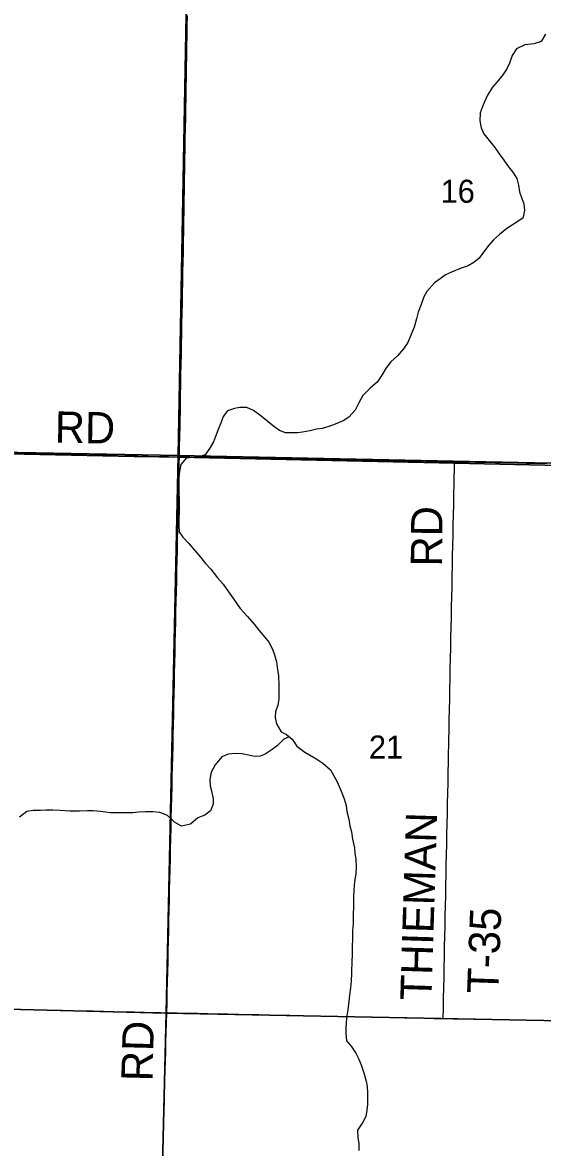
# Model space of a CAD drawing. Extents: x 0 to 34, y 0 to 22.
# Drawn here: x 3.484 to 4.43, y 15.194 to 17.239 of the extents above; entities that cross this region are included whole.
import ezdxf

# ---------------------------------------------------------------- set-up
doc = ezdxf.new("R2010")
doc.units = 0
for name, color, linetype in [('GM_X_Corporation', 7, 'Continuous'), ('GM_X_County_Road', 7, 'Continuous'), ('GM_X_County_Road_Text', 7, 'Continuous'), ('GM_X_Minor_River', 7, 'Continuous'), ('GM_X_Section_Text', 7, 'Continuous'), ('GM_X_State_Route', 7, 'Continuous'), ('GM_X_Township_Road', 7, 'Continuous'), ('GM_X_Township_Road_Text', 7, 'Continuous')]:
    doc.layers.add(name, color=color, linetype=linetype)

msp = doc.modelspace()

# ---------------------------------------------------------------- linework, layer by layer
at = {"layer": 'GM_X_Corporation'}
for points in [[(3.5996, 19.4692), (2.7976, 19.484), (2.7779, 19.4843), (2.1, 19.4964), (2.1, 16.485), (2.253, 16.4822), (2.4333, 16.478), (2.4403, 16.4778), (2.5826, 16.473), (2.7595, 16.4724), (3.1897, 16.4617), (3.4295, 16.4557), (3.687, 16.4502), (3.6948, 16.4501), (3.7682, 16.4494), (4.2697, 16.4379), (4.8738, 16.4249)], [(4.8738, 16.4249), (4.2697, 16.4379), (3.7682, 16.4494), (3.6948, 16.4501), (3.687, 16.4502), (3.4295, 16.4557), (3.1897, 16.4617), (2.7595, 16.4724), (2.5826, 16.473), (2.4403, 16.4778), (2.4333, 16.478), (2.253, 16.4822), (2.1, 16.485), (2.1, 14.1), (7.7244, 14.1)]]:
    msp.add_lwpolyline(points, dxfattribs=at)
for points in [[(3.785, 17.4549), (3.7672, 16.4521), (2.7618, 16.4707), (2.771, 17.4824)], [(4.7862, 17.4375), (4.7695, 16.4317), (3.7672, 16.4521), (3.785, 17.4549)], [(2.7618, 16.4707), (3.7672, 16.4521), (3.745, 15.438), (2.7333, 15.4639)], [(4.7695, 16.4317), (4.7451, 15.4188), (3.745, 15.438), (3.7672, 16.4521)], [(3.745, 15.438), (3.7208, 14.432), (2.7064, 14.4541), (2.7333, 15.4639)], [(4.7451, 15.4188), (4.7262, 14.4138), (3.7208, 14.432), (3.745, 15.438)]]:
    msp.add_lwpolyline(points, close=True, dxfattribs=at)
at = {"layer": 'GM_X_County_Road'}
msp.add_lwpolyline([(3.4702, 16.4561), (3.4889, 16.4558), (3.5075, 16.4554), (3.5261, 16.455), (3.5448, 16.4546), (3.5634, 16.4542), (3.582, 16.4538), (3.6007, 16.4534), (3.6193, 16.453), (3.6379, 16.4526), (3.6566, 16.4522), (3.6752, 16.4518), (3.6938, 16.4514), (3.7125, 16.451), (3.7311, 16.4506), (3.7497, 16.4502), (3.7596, 16.45), (3.7694, 16.4498), (3.7881, 16.4495), (3.8067, 16.4492), (3.8253, 16.4488), (3.844, 16.4485), (3.8626, 16.4482), (3.8813, 16.4478), (3.8999, 16.4475), (3.9185, 16.4472), (3.9372, 16.4468), (3.9558, 16.4465), (3.9745, 16.4462), (3.9931, 16.4458), (4.0117, 16.4455), (4.0304, 16.4452), (4.049, 16.4448), (4.0677, 16.4445), (4.0863, 16.4442), (4.105, 16.4438), (4.1236, 16.4435), (4.1422, 16.4432), (4.1609, 16.4428), (4.1795, 16.4425), (4.1982, 16.4422), (4.2168, 16.4418), (4.2354, 16.4415), (4.2528, 16.4412), (4.2701, 16.4409), (4.2887, 16.4405), (4.3074, 16.4402), (4.326, 16.4398), (4.3446, 16.4395), (4.3633, 16.4391), (4.3819, 16.4388), (4.4005, 16.4384), (4.4192, 16.4381), (4.4378, 16.4377)], dxfattribs=at)
at = {"layer": 'GM_X_Minor_River'}
for points in [[(4.4358, 17.2183), (4.428, 17.2051), (4.4146, 17.2009), (4.3979, 17.1986), (4.3829, 17.1917), (4.3747, 17.1794), (4.3702, 17.1654), (4.3654, 17.1549), (4.358, 17.144), (4.3475, 17.1317), (4.3389, 17.1216), (4.3302, 17.1074), (4.3243, 17.0949), (4.3203, 17.0851), (4.3166, 17.0753), (4.3159, 17.0609), (4.3183, 17.0479), (4.3234, 17.0371), (4.3356, 17.022), (4.3437, 17.0123), (4.3514, 17.0007), (4.3595, 16.9891), (4.3665, 16.9795), (4.3772, 16.9655), (4.3834, 16.9559), (4.3866, 16.9436), (4.3882, 16.9318), (4.3925, 16.9195), (4.3961, 16.9099), (4.3977, 16.8977), (4.3944, 16.8837), (4.3786, 16.8735), (4.3651, 16.8647), (4.3516, 16.8539), (4.3411, 16.8443), (4.3326, 16.8346), (4.3228, 16.8219), (4.315, 16.8107), (4.3053, 16.8033), (4.2946, 16.7971), (4.2823, 16.7928), (4.2647, 16.7856), (4.2536, 16.7805), (4.244, 16.7735), (4.2339, 16.7658), (4.2199, 16.7505), (4.214, 16.7404), (4.2092, 16.7268), (4.2039, 16.7129), (4.201, 16.7008), (4.1965, 16.6857), (4.1905, 16.671), (4.1853, 16.6578), (4.1774, 16.6462), (4.1665, 16.6332), (4.1541, 16.6224), (4.1459, 16.6116), (4.1377, 16.5981), (4.1294, 16.5854), (4.1174, 16.575), (4.1031, 16.5613), (4.0959, 16.5481), (4.0892, 16.5346), (4.0775, 16.5219), (4.0675, 16.515), (4.053, 16.5088), (4.0415, 16.5049), (4.0289, 16.501), (4.0186, 16.4998), (4.0068, 16.497)], [(4.0068, 16.497), (3.9935, 16.4946), (3.984, 16.4933), (3.9726, 16.4932), (3.9623, 16.4935), (3.9514, 16.4975), (3.941, 16.5046), (3.9272, 16.5163), (3.9156, 16.5257), (3.9041, 16.534), (3.892, 16.5392), (3.8791, 16.5391), (3.8696, 16.5378), (3.857, 16.5335), (3.8492, 16.5231), (3.8452, 16.5129), (3.8399, 16.4997), (3.8351, 16.4869), (3.8311, 16.4767), (3.8255, 16.4666), (3.8161, 16.4531), (3.8039, 16.4489), (3.7944, 16.4483), (3.7815, 16.4471), (3.7721, 16.4355), (3.7691, 16.4196), (3.7681, 16.4094), (3.7682, 16.3965), (3.7684, 16.3862), (3.7687, 16.3695), (3.7688, 16.355), (3.7683, 16.333), (3.7685, 16.3228), (3.769, 16.3132), (3.7756, 16.3036), (3.7864, 16.2919), (3.7967, 16.2799), (3.8078, 16.2675), (3.817, 16.2555), (3.8263, 16.2454), (3.8384, 16.2295), (3.8488, 16.2183), (3.8587, 16.2044), (3.8676, 16.1916), (3.8801, 16.1742), (3.893, 16.1595), (3.9052, 16.1455), (3.9137, 16.1347), (3.9241, 16.1227), (3.9318, 16.113), (3.9387, 16.0999), (3.9427, 16.0896), (3.9462, 16.077), (3.9475, 16.0674), (3.9494, 16.0514), (3.9505, 16.0347), (3.9506, 16.0229), (3.9503, 16.0096), (3.9482, 15.9975), (3.9441, 15.9866), (3.9435, 15.976), (3.9463, 15.9641), (3.9543, 15.9499), (3.9644, 15.9447), (3.9745, 15.9365), (3.9833, 15.9238), (3.9975, 15.9128), (4.0091, 15.9061), (4.0196, 15.9001), (4.0304, 15.893), (4.0442, 15.8809), (4.0504, 15.8698), (4.0566, 15.859), (4.0638, 15.8417), (4.0695, 15.8279), (4.0727, 15.8157), (4.0743, 15.805), (4.0778, 15.7909), (4.0794, 15.7787), (4.0826, 15.7676), (4.0846, 15.7543), (4.088, 15.739), (4.0889, 15.7291), (4.0906, 15.7173), (4.091, 15.7043), (4.0904, 15.6922), (4.0881, 15.6767), (4.0871, 15.6627), (4.0864, 15.649), (4.0853, 15.6004), (4.0846, 15.5886), (4.0836, 15.5435), (4.083, 15.5336), (4.0825, 15.5116), (4.0818, 15.4964), (4.0807, 15.4843), (4.0789, 15.4707), (4.0775, 15.4597), (4.0757, 15.4441), (4.0743, 15.4335), (4.0729, 15.421)], [(3.9692, 15.9409), (3.9597, 15.9365), (3.9477, 15.925), (3.938, 15.9176), (3.9257, 15.9091), (3.9161, 15.9056), (3.9059, 15.9047), (3.8953, 15.9072), (3.8836, 15.9097), (3.8707, 15.9104), (3.8578, 15.9092), (3.8463, 15.9045), (3.8342, 15.89), (3.8271, 15.8765), (3.8249, 15.8628), (3.8254, 15.8518), (3.8275, 15.8423), (3.8309, 15.8281), (3.8307, 15.8183), (3.8259, 15.8058), (3.8158, 15.7981), (3.8028, 15.7935), (3.7897, 15.782), (3.7729, 15.7782), (3.7606, 15.7857), (3.7475, 15.7974), (3.734, 15.803), (3.7211, 15.8041), (3.7079, 15.8044), (3.6957, 15.8035), (3.6843, 15.8023), (3.6703, 15.8022), (3.6555, 15.8026), (3.6437, 15.8025), (3.6259, 15.8048), (3.6123, 15.8058), (3.6021, 15.8061), (3.5873, 15.8057), (3.5698, 15.8057), (3.5524, 15.8069), (3.5387, 15.8075), (3.527, 15.8071), (3.5163, 15.8065), (3.5031, 15.8065), (3.4916, 15.8048), (3.4781, 15.7945)], [(4.0729, 15.421), (4.0723, 15.4112), (4.072, 15.4013), (4.0736, 15.388), (4.0821, 15.3783), (4.0906, 15.3656), (4.096, 15.3548), (4.1007, 15.3422), (4.1049, 15.3295), (4.1091, 15.3146), (4.1108, 15.3051), (4.1117, 15.294), (4.1118, 15.283), (4.1116, 15.272), (4.1106, 15.2618), (4.1088, 15.2501), (4.1029, 15.2403), (4.0935, 15.2253), (4.0939, 15.2124), (4.0956, 15.2006), (4.0957, 15.1885)]]:
    msp.add_lwpolyline(points, dxfattribs=at)
at = {"layer": 'GM_X_State_Route'}
msp.add_lwpolyline([(3.4821, 15.4452), (3.5007, 15.4447), (3.5193, 15.4443), (3.538, 15.4439), (3.5566, 15.4434), (3.5753, 15.443), (3.5939, 15.4426), (3.6125, 15.4422), (3.6312, 15.4417), (3.6498, 15.4413), (3.6684, 15.4409), (3.6871, 15.4404), (3.7057, 15.44), (3.7243, 15.4396), (3.7354, 15.4393), (3.7465, 15.439), (3.7651, 15.4387), (3.7837, 15.4383), (3.8024, 15.4379), (3.821, 15.4375), (3.8397, 15.4371), (3.8583, 15.4367), (3.8769, 15.4363), (3.8956, 15.4359), (3.9142, 15.4355), (3.9328, 15.4351), (3.9515, 15.4347), (3.9701, 15.4343), (3.9887, 15.4339), (4.0074, 15.4335), (4.026, 15.4331), (4.0446, 15.4327), (4.0633, 15.4324), (4.0819, 15.432), (4.1005, 15.4316), (4.1121, 15.4313), (4.1237, 15.4311), (4.1423, 15.4307), (4.1609, 15.4303), (4.1796, 15.4299), (4.1982, 15.4295), (4.2168, 15.4291), (4.2331, 15.4288), (4.2494, 15.4284), (4.268, 15.4281), (4.2867, 15.4278), (4.3053, 15.4274), (4.324, 15.4271), (4.3426, 15.4268), (4.3612, 15.4265), (4.3799, 15.4261), (4.3985, 15.4258), (4.4172, 15.4255), (4.4358, 15.4251)], dxfattribs=at)
at = {"layer": 'GM_X_Township_Road'}
for points in [[(3.7694, 16.4498), (3.7698, 16.4685), (3.7701, 16.4871), (3.7705, 16.5057), (3.7712, 16.543), (3.7715, 16.5616), (3.7719, 16.5803), (3.7722, 16.5989), (3.7726, 16.6175), (3.7729, 16.6362), (3.7733, 16.6548), (3.7737, 16.6734), (3.774, 16.6921), (3.7744, 16.7107), (3.7747, 16.7293), (3.7751, 16.748), (3.7754, 16.7666), (3.7758, 16.7852), (3.7761, 16.8039), (3.7765, 16.8225), (3.7768, 16.8411), (3.7772, 16.8598), (3.7775, 16.8784), (3.7779, 16.8971), (3.7782, 16.9157), (3.7786, 16.9343), (3.7787, 16.9441), (3.7789, 16.9538), (3.7792, 16.9725), (3.7795, 16.9911), (3.7798, 17.0098), (3.7801, 17.0284), (3.7805, 17.0471), (3.7808, 17.0657), (3.7811, 17.0843), (3.7814, 17.103), (3.7817, 17.1216), (3.782, 17.1403), (3.7823, 17.1589), (3.7826, 17.1775), (3.7829, 17.1962), (3.7832, 17.2148), (3.7835, 17.2335), (3.7838, 17.2521)], [(3.7393, 15.1869), (3.7398, 15.2055), (3.7404, 15.2242), (3.7409, 15.2428), (3.7414, 15.2614), (3.742, 15.2801), (3.7425, 15.2987), (3.7428, 15.3087), (3.7431, 15.3187), (3.7435, 15.3352), (3.744, 15.3517), (3.7444, 15.3663), (3.7449, 15.385), (3.7455, 15.4036), (3.746, 15.4213), (3.7465, 15.439), (3.7469, 15.4577), (3.7473, 15.4763), (3.7478, 15.495), (3.7482, 15.5136), (3.7486, 15.5322), (3.7491, 15.5509), (3.7495, 15.5695), (3.7499, 15.5881), (3.7503, 15.6068), (3.7508, 15.6254), (3.7512, 15.644), (3.7516, 15.6627), (3.7521, 15.6813), (3.7525, 15.6999), (3.7529, 15.7186), (3.7533, 15.7372), (3.7538, 15.7558), (3.7542, 15.7745), (3.7546, 15.7931), (3.7551, 15.8117), (3.7555, 15.8304), (3.7559, 15.849), (3.7564, 15.8676), (3.7568, 15.8863), (3.7572, 15.9049), (3.7577, 15.9236), (3.7579, 15.934), (3.7581, 15.9444), (3.7586, 15.9631), (3.759, 15.9817), (3.7594, 16.0003), (3.7598, 16.019), (3.7602, 16.0376), (3.7606, 16.0562), (3.7611, 16.0749), (3.7615, 16.0935), (3.7619, 16.1121), (3.7623, 16.1308), (3.7627, 16.1494), (3.7631, 16.168), (3.7636, 16.1867), (3.764, 16.2053), (3.7644, 16.2239), (3.7648, 16.2426), (3.7652, 16.2612), (3.7656, 16.2799), (3.7661, 16.2985), (3.7665, 16.3171), (3.7669, 16.3358), (3.7673, 16.3544), (3.7677, 16.373), (3.7681, 16.3917), (3.7685, 16.4103), (3.7689, 16.4289), (3.7692, 16.4394), (3.7694, 16.4498)], [(4.2494, 15.4284), (4.2498, 15.4471), (4.2502, 15.4657), (4.2505, 15.4843), (4.2509, 15.503), (4.2513, 15.5216), (4.2517, 15.5402), (4.2521, 15.5589), (4.2524, 15.5775), (4.2528, 15.5961), (4.2532, 15.6148), (4.2536, 15.6334), (4.254, 15.652), (4.2543, 15.6707), (4.2547, 15.6893), (4.2551, 15.7079), (4.2555, 15.7266), (4.2559, 15.7452), (4.2563, 15.7638), (4.2566, 15.7825), (4.257, 15.8011), (4.2574, 15.8197), (4.2578, 15.8384), (4.2582, 15.857), (4.2585, 15.8757), (4.2589, 15.8943), (4.2593, 15.9129), (4.2595, 15.9237), (4.2598, 15.9345), (4.2601, 15.9531), (4.2605, 15.9717), (4.2609, 15.9904), (4.2613, 16.009), (4.2616, 16.0276), (4.262, 16.0463), (4.2624, 16.0649), (4.2628, 16.0835), (4.2632, 16.1022), (4.2635, 16.1208), (4.2639, 16.1394), (4.2643, 16.1581), (4.2647, 16.1767), (4.2651, 16.1954), (4.2655, 16.214), (4.2658, 16.2326), (4.2662, 16.2513), (4.2666, 16.2699), (4.267, 16.2885), (4.2674, 16.3072), (4.2677, 16.3258), (4.2681, 16.3444), (4.2685, 16.3631), (4.2689, 16.3817), (4.2693, 16.4003), (4.2695, 16.4128), (4.2698, 16.4253), (4.2701, 16.4409)]]:
    msp.add_lwpolyline(points, dxfattribs=at)

# ---------------------------------------------------------------- texts
at = {"layer": 'GM_X_County_Road_Text'}
msp.add_text('RD', height=0.05682, rotation=359.0118, dxfattribs=at).set_placement((3.5422, 16.4756))
at = {"layer": 'GM_X_Section_Text'}
for s, p in [('16', (4.2447, 16.9117)), ('21', (4.1143, 15.9011))]:
    msp.add_text(s, height=0.04186, rotation=0, dxfattribs=at).set_placement(p)
at = {"layer": 'GM_X_Township_Road_Text'}
for s, rotation, p in [('RD', 89.5063, (4.2472, 16.2501)), ('THIEMAN', 88.2333, (4.228, 15.4608)), ('T-35', 87.9255, (4.3496, 15.473)), ('RD', 88.5184, (3.7203, 15.3138))]:
    msp.add_text(s, height=0.05682, rotation=rotation, dxfattribs=at).set_placement(p)

doc.saveas('drawing.dxf')
